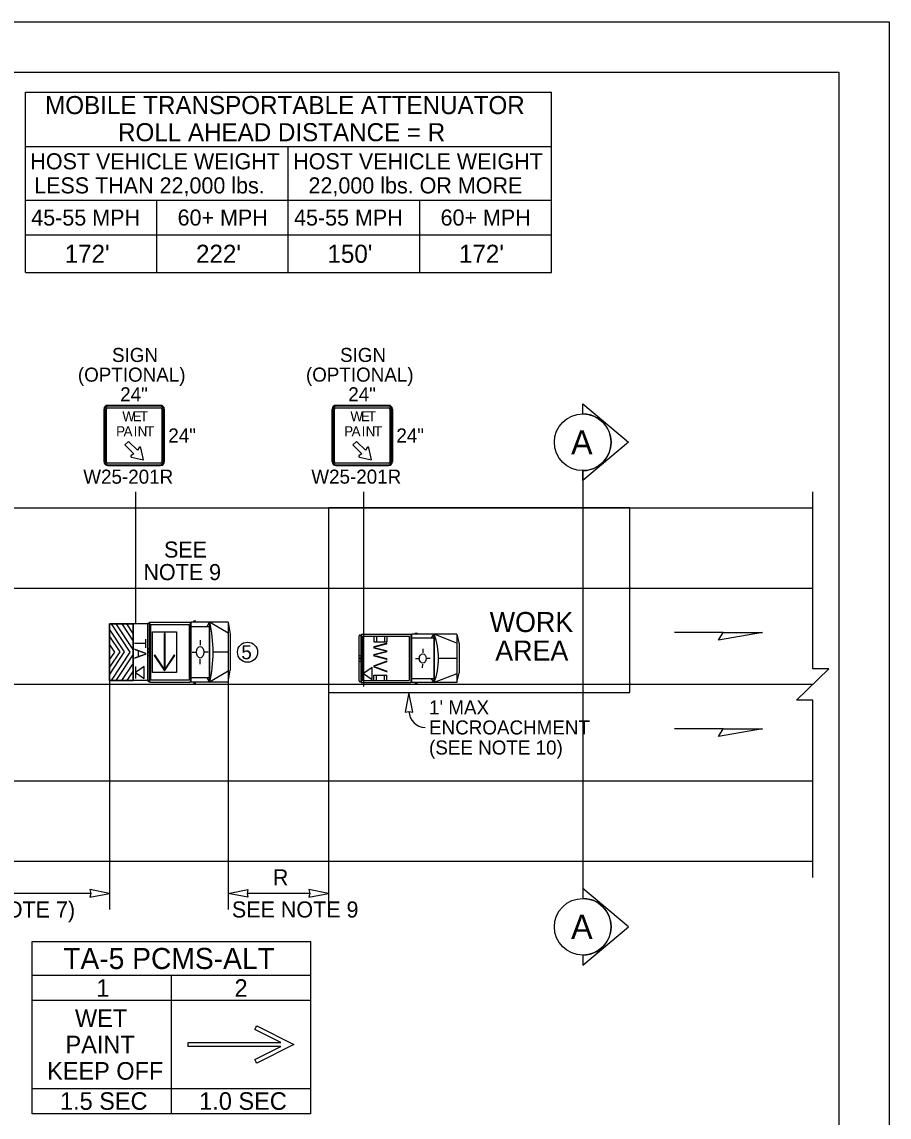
# Model space of a CAD drawing. Extents: x 0 to 17, y 0 to 11.
# Drawn here: x 12.68 to 17, y 5.55 to 11 of the extents above; entities that cross this region are included whole.
import ezdxf

# ---------------------------------------------------------------- set-up
doc = ezdxf.new("R2010")
doc.units = 0
for name, color, linetype in [('RD_ED_ShoulderPavedEdge', 7, 'Continuous'), ('RD_MK_LineEdgeWhite', 7, 'Continuous'), ('RD_MK_LineEdgeYellow', 7, 'Continuous'), ('RD_MK_LineLane', 7, 'Continuous'), ('SH_GI_PlotLimits', 7, 'Continuous'), ('SH_GI_SheetBorder3', 7, 'Continuous'), ('SH_TI_Tables', 7, 'Continuous'), ('SH_TI_WZSectionCut', 7, 'Continuous'), ('TR_SN_ConstructionSigns', 7, 'Continuous'), ('TR_WZ_PortableChangeMessageSign', 7, 'Continuous'), ('TR_WZ_PortableSignMountBlk-Org', 7, 'Continuous'), ('TR_WZ_ProtectiveVehicle', 7, 'Continuous'), ('TR_WZ_TransportableAttenuator', 7, 'Continuous'), ('TR_WZ_WorkZoneDetails', 7, 'Continuous'), ('TR_WZ_WorkZoneTextCurrent', 7, 'Continuous')]:
    doc.layers.add(name, color=color, linetype=linetype)

msp = doc.modelspace()

# ---------------------------------------------------------------- linework, layer by layer
at = {"layer": 'RD_ED_ShoulderPavedEdge'}
for p, q in [((1.8283, 8.5807), (16.62, 8.5807)), ((1.8283, 6.8207), (16.62, 6.8207))]:
    msp.add_line(p, q, dxfattribs=at)
at = {"layer": 'RD_MK_LineEdgeWhite'}
msp.add_line((1.8283, 7.2207), (16.62, 7.2207), dxfattribs=at)
at = {"layer": 'RD_MK_LineEdgeYellow'}
msp.add_line((1.8283, 8.1807), (16.62, 8.1807), dxfattribs=at)
at = {"layer": 'RD_MK_LineLane'}
msp.add_line((16.62, 7.7007), (1.8283, 7.7007), dxfattribs=at)
at = {"layer": 'SH_GI_PlotLimits'}
msp.add_lwpolyline([(0, 11), (17, 11), (17, 0), (0, 0)], close=True, dxfattribs=at)
at = {"layer": 'SH_GI_SheetBorder3'}
for p, q in [((1, 10.75), (16.75, 10.75)), ((16.75, 10.75), (16.75, 0.25))]:
    msp.add_line(p, q, dxfattribs=at)
at = {"layer": 'SH_TI_Tables'}
for p, q in [((12.7019, 9.7515), (12.7019, 10.65)), ((12.7019, 10.65), (15.3188, 10.65)), ((15.3188, 9.7515), (15.3188, 10.65)), ((12.7019, 10.3797), (15.3188, 10.3797)), ((14.0096, 9.7515), (14.0096, 10.3797)), ((12.7019, 10.1123), (14.0096, 10.1123)), ((13.3557, 9.7515), (13.3557, 10.1123)), ((14.0096, 10.1123), (15.3188, 10.1123)), ((14.6642, 9.7515), (14.6642, 10.1123)), ((12.7019, 9.9395), (13.3557, 9.9395)), ((13.3557, 9.9395), (14.0096, 9.9395)), ((14.0096, 9.9395), (14.6642, 9.9395)), ((14.6642, 9.9395), (15.3188, 9.9395)), ((12.7019, 9.7515), (15.3188, 9.7515))]:
    msp.add_line(p, q, dxfattribs=at)
at = {"layer": 'SH_TI_WZSectionCut'}
for p, q in [((15.4753, 9.0481), (15.4753, 9.098)), ((15.4753, 9.098), (15.7034, 8.9069)), ((15.7034, 8.9069), (15.4753, 8.7158)), ((15.4753, 8.7158), (15.4753, 8.7657)), ((15.4753, 8.7657), (15.4753, 6.6358)), ((15.4753, 6.6857), (15.4753, 6.6358)), ((15.7034, 6.4945), (15.4753, 6.6857)), ((15.4753, 6.3034), (15.7034, 6.4945)), ((15.4753, 6.3533), (15.4753, 6.3034))]:
    msp.add_line(p, q, dxfattribs=at)
for centre in [(15.4753, 8.9069), (15.4753, 6.4945)]:
    msp.add_circle(centre, 0.1412, dxfattribs=at)
for centre in [(15.4753, 8.9069), (15.4753, 6.4945)]:
    msp.add_arc(centre, 0.1412, 269.9978, 90.0022, dxfattribs=at)
at = {"layer": 'TR_SN_ConstructionSigns'}
for p, q in [((13.0922, 9.072), (13.0922, 8.8095)), ((13.0922, 8.8095), (13.0922, 9.072)), ((13.0922, 9.072), (13.0922, 8.8095)), ((13.0969, 9.072), (13.0969, 8.8095)), ((13.1047, 8.8095), (13.1047, 9.072)), ((13.3735, 9.0907), (13.111, 9.0907)), ((13.111, 9.0907), (13.3735, 9.0907)), ((13.3735, 9.0907), (13.111, 9.0907)), ((13.3735, 9.086), (13.111, 9.086)), ((13.111, 9.0782), (13.3735, 9.0782)), ((13.3797, 9.072), (13.3797, 8.8095)), ((13.3875, 8.8095), (13.3875, 9.072)), ((13.3922, 8.8095), (13.3922, 9.072)), ((13.3922, 9.072), (13.3922, 8.8095)), ((13.3922, 8.8095), (13.3922, 9.072)), ((14.2274, 9.072), (14.2274, 8.8095)), ((14.2274, 8.8095), (14.2274, 9.072)), ((14.2274, 9.072), (14.2274, 8.8095)), ((14.2321, 9.072), (14.2321, 8.8095)), ((14.2399, 8.8095), (14.2399, 9.072)), ((14.5086, 9.0908), (14.2461, 9.0908)), ((14.2461, 9.0908), (14.5086, 9.0908)), ((14.5086, 9.0908), (14.2461, 9.0908)), ((14.5086, 9.0861), (14.2461, 9.0861)), ((14.2461, 9.0783), (14.5086, 9.0783)), ((14.5149, 9.072), (14.5149, 8.8095)), ((14.5227, 8.8095), (14.5227, 9.072)), ((14.5274, 8.8095), (14.5274, 9.072)), ((14.5274, 9.072), (14.5274, 8.8095)), ((14.5274, 8.8095), (14.5274, 9.072)), ((13.214, 8.9116), (13.1964, 8.8939)), ((13.1964, 8.8939), (13.2406, 8.8497)), ((13.2582, 8.8674), (13.214, 8.9116)), ((14.3492, 8.9116), (14.3315, 8.8939)), ((14.3315, 8.8939), (14.3757, 8.8497)), ((14.3934, 8.8674), (14.3492, 8.9116)), ((13.2406, 8.8497), (13.2271, 8.8416)), ((13.2664, 8.8809), (13.2582, 8.8674)), ((13.2881, 8.8199), (13.2749, 8.8796)), ((14.3757, 8.8497), (14.3622, 8.8416)), ((14.4015, 8.8809), (14.3934, 8.8674)), ((14.4232, 8.8199), (14.4101, 8.8796)), ((13.3735, 8.8032), (13.111, 8.8032)), ((13.111, 8.7954), (13.3735, 8.7954)), ((13.111, 8.7907), (13.3735, 8.7907)), ((13.3735, 8.7907), (13.111, 8.7907)), ((13.111, 8.7907), (13.3735, 8.7907)), ((13.2283, 8.833), (13.2881, 8.8199)), ((14.5086, 8.8033), (14.2461, 8.8033)), ((14.2461, 8.7954), (14.5086, 8.7954)), ((14.2461, 8.7908), (14.5086, 8.7908)), ((14.5086, 8.7908), (14.2461, 8.7908)), ((14.2461, 8.7908), (14.5086, 8.7908)), ((14.3635, 8.833), (14.4232, 8.8199))]:
    msp.add_line(p, q, dxfattribs=at)
for centre, radius, start, end in [((13.111, 9.072), 0.0188, 90, 180), ((13.111, 9.072), 0.0188, 90, 180), ((13.111, 9.072), 0.0188, 90, 180), ((13.111, 9.072), 0.0141, 90, 180), ((13.111, 9.072), 0.00625, 90, 180), ((13.3735, 9.072), 0.0188, 0, 90), ((13.3735, 9.072), 0.0188, 0, 90), ((13.3735, 9.072), 0.0188, 0, 90), ((13.3735, 9.072), 0.0141, 0, 90), ((13.3735, 9.072), 0.00625, 0, 90), ((14.2461, 9.072), 0.0188, 90, 180), ((14.2461, 9.072), 0.0188, 90, 180), ((14.2461, 9.072), 0.0188, 90, 180), ((14.2461, 9.072), 0.0141, 90, 180), ((14.2461, 9.072), 0.00625, 90, 180), ((14.5086, 9.072), 0.0188, 0, 90), ((14.5086, 9.072), 0.0188, 0, 90), ((14.5086, 9.072), 0.0188, 0, 90), ((14.5086, 9.072), 0.0141, 0, 90), ((14.5086, 9.072), 0.00625, 0, 90), ((13.2295, 8.8376), 0.00469, 121.1441, 255.4258), ((13.2704, 8.8784), 0.00469, 14.5742, 148.8559), ((14.3647, 8.8376), 0.00469, 121.1441, 255.4258), ((14.4055, 8.8785), 0.00469, 14.5742, 148.8559), ((13.111, 8.8095), 0.0188, 180, 270), ((13.111, 8.8095), 0.0188, 180, 270), ((13.111, 8.8095), 0.0188, 180, 270), ((13.111, 8.8095), 0.0141, 180, 270), ((13.111, 8.8095), 0.00625, 180, 270), ((13.3735, 8.8095), 0.0141, 270, 0), ((13.3735, 8.8095), 0.00625, 270, 0), ((13.3735, 8.8095), 0.0188, 270, 0), ((13.3735, 8.8095), 0.0188, 270, 0), ((13.3735, 8.8095), 0.0188, 270, 0), ((14.2461, 8.8095), 0.0188, 180, 270), ((14.2461, 8.8095), 0.0188, 180, 270), ((14.2461, 8.8095), 0.0188, 180, 270), ((14.2461, 8.8095), 0.0141, 180, 270), ((14.2461, 8.8095), 0.00625, 180, 270), ((14.5086, 8.8095), 0.0141, 270, 0), ((14.5086, 8.8095), 0.00625, 270, 0), ((14.5086, 8.8095), 0.0188, 270, 0), ((14.5086, 8.8095), 0.0188, 270, 0), ((14.5086, 8.8095), 0.0188, 270, 0)]:
    msp.add_arc(centre, radius, start, end, dxfattribs=at)
at = {"layer": 'TR_WZ_PortableChangeMessageSign'}
for p, q in [((12.7348, 6.4207), (14.1208, 6.4207)), ((12.7348, 5.5639), (12.7348, 6.4207)), ((14.1208, 5.5639), (14.1208, 6.4207)), ((14.1208, 6.2527), (12.7348, 6.2527)), ((13.4278, 5.5639), (13.4278, 6.2527)), ((13.4278, 6.1267), (12.7348, 6.1267)), ((14.1208, 6.1267), (13.4278, 6.1267)), ((13.8528, 6.0017), (14.0368, 5.9083)), ((13.5118, 5.8978), (13.5118, 5.9188)), ((13.5118, 5.9188), (13.9716, 5.9188)), ((13.9716, 5.8978), (13.5118, 5.8978)), ((12.7348, 5.6899), (13.4278, 5.6899)), ((13.4278, 5.6899), (14.1208, 5.6899)), ((14.1208, 5.5639), (12.7348, 5.5639))]:
    msp.add_line(p, q, dxfattribs=at)
for points in [[(13.9716, 5.9188), (13.8434, 5.9829), (13.8481, 5.9923), (13.8528, 6.0017)], [(14.0368, 5.9083), (13.8528, 5.8149), (13.8481, 5.8243), (13.8434, 5.8337), (13.9716, 5.8978)]]:
    msp.add_lwpolyline(points, dxfattribs=at)
at = {"layer": 'TR_WZ_PortableSignMountBlk-Org'}
for p, q in [((13.2487, 7.7904), (13.2487, 7.7304)), ((14.3839, 7.7853), (14.3839, 7.7253))]:
    msp.add_line(p, q, dxfattribs=at)
for points in [[(13.2487, 7.7604), (13.2918, 7.7304), (13.2918, 7.7904)], [(14.3839, 7.7553), (14.427, 7.7253), (14.427, 7.7853)]]:
    msp.add_lwpolyline(points, close=True, dxfattribs=at)
at = {"layer": 'TR_WZ_ProtectiveVehicle'}
for p, q in [((14.3603, 7.9394), (14.3603, 7.722)), ((14.3657, 7.9468), (14.3711, 7.9468)), ((14.3711, 7.9468), (14.3711, 7.7146)), ((14.3719, 7.9507), (14.6187, 7.9507)), ((14.3719, 7.9507), (14.3719, 7.7107)), ((14.3789, 7.9411), (14.3789, 7.7203)), ((14.3789, 7.9411), (14.6117, 7.9411)), ((14.4345, 7.9411), (14.4345, 7.9135)), ((14.4345, 7.9135), (14.5005, 7.9135)), ((14.4477, 7.9411), (14.4477, 7.9135)), ((14.4885, 7.9411), (14.4885, 7.9135)), ((14.5005, 7.9411), (14.5005, 7.9135)), ((14.6117, 7.9411), (14.6117, 7.7203)), ((14.6187, 7.9507), (14.6187, 7.7107)), ((14.622, 7.9507), (14.622, 7.7107)), ((14.8487, 7.9507), (14.622, 7.9507)), ((14.7333, 7.9321), (14.622, 7.9321)), ((14.653, 7.9541), (14.6394, 7.9541)), ((14.7333, 7.9507), (14.7189, 7.9321)), ((14.7333, 7.9507), (14.7333, 7.7107)), ((14.7354, 7.9507), (14.7354, 7.7107)), ((14.8487, 7.9068), (14.7354, 7.9507)), ((14.8487, 7.9507), (14.8487, 7.7107)), ((14.8487, 7.9507), (14.8599, 7.9022)), ((14.6789, 7.8783), (14.6789, 7.8589)), ((14.8599, 7.9022), (14.8599, 7.7591)), ((14.3603, 7.8476), (14.3711, 7.8431)), ((14.3603, 7.8138), (14.3711, 7.8183)), ((14.3632, 7.8307), (14.3682, 7.8307)), ((14.3657, 7.8341), (14.3657, 7.8273)), ((14.6419, 7.8298), (14.6597, 7.8302)), ((14.662, 7.8303), (14.662, 7.8303)), ((14.6781, 7.7845), (14.6784, 7.8026)), ((14.7151, 7.8309), (14.7, 7.8308)), ((14.8487, 7.8307), (14.7576, 7.8307)), ((14.4345, 7.7203), (14.4345, 7.7479)), ((14.4345, 7.7479), (14.5005, 7.7479)), ((14.4477, 7.7203), (14.4477, 7.7479)), ((14.4885, 7.7203), (14.4885, 7.7479)), ((14.5005, 7.7203), (14.5005, 7.7479)), ((14.8487, 7.7546), (14.7354, 7.7107)), ((14.8487, 7.7107), (14.8599, 7.7591)), ((14.3657, 7.7146), (14.3711, 7.7146)), ((14.3719, 7.7107), (14.6187, 7.7107)), ((14.3789, 7.7203), (14.6117, 7.7203)), ((14.7333, 7.7293), (14.622, 7.7293)), ((14.8487, 7.7107), (14.622, 7.7107)), ((14.653, 7.7073), (14.6394, 7.7073)), ((14.7214, 7.7293), (14.7333, 7.7107))]:
    msp.add_line(p, q, dxfattribs=at)
for centre, major_axis, start_param, end_param in [((14.3657, 7.9394), (0, 0.00732), 6.283185, 7.853982), ((14.5734, 7.8307), (0, 0.2518), 4.215852, 5.209111), ((14.3657, 7.722), (0, -0.00732), 4.712389, 6.283185)]:
    msp.add_ellipse(centre, major_axis=major_axis, ratio=0.73155, start_param=start_param, end_param=end_param, dxfattribs=at)
for centre, major_axis in [((14.6789, 7.8307), (0, -0.0231)), ((14.3657, 7.8307), (0, -0.00338))]:
    msp.add_ellipse(centre, major_axis=major_axis, ratio=0.73155, dxfattribs=at)
at = {"layer": 'TR_WZ_TransportableAttenuator'}
for p, q in [((13.1195, 7.9395), (13.1195, 7.976)), ((13.1947, 7.8628), (13.1195, 7.976)), ((13.1195, 7.976), (13.1195, 7.9395)), ((13.1273, 8.0028), (13.1528, 8.0028)), ((13.1273, 8.0028), (13.2209, 7.862)), ((13.1528, 8.0028), (13.1273, 8.0028)), ((13.2375, 7.8744), (13.1528, 8.0028)), ((13.1805, 8.0028), (13.2059, 8.0028)), ((13.2059, 8.0028), (13.1805, 8.0028)), ((13.1805, 8.0028), (13.2375, 7.9159)), ((13.2375, 7.9551), (13.2059, 8.0028)), ((13.318, 8.0028), (13.2375, 8.0028)), ((13.2375, 7.7212), (13.2375, 8.0028)), ((13.3085, 7.9976), (13.3085, 7.7257)), ((13.3129, 8.0067), (13.3173, 8.0067)), ((13.3173, 8.0067), (13.3173, 7.7166)), ((13.318, 8.0117), (13.5211, 8.0117)), ((13.318, 8.0117), (13.318, 7.7117)), ((13.318, 8.0023), (13.318, 7.7212)), ((13.3237, 7.9997), (13.3237, 7.7237)), ((13.3237, 7.9997), (13.5154, 7.9997)), ((13.5154, 7.9997), (13.5154, 7.7237)), ((13.5211, 8.0117), (13.5211, 7.7117)), ((13.5239, 8.0117), (13.5239, 7.7117)), ((13.7104, 8.0117), (13.5239, 8.0117)), ((13.6154, 7.9884), (13.5239, 7.9884)), ((13.5493, 8.0159), (13.5381, 8.0159)), ((13.6154, 8.0117), (13.6036, 7.9884)), ((13.6154, 8.0117), (13.6154, 7.7117)), ((13.6171, 8.0117), (13.6171, 7.7117)), ((13.7104, 7.9567), (13.6171, 8.0117)), ((13.7104, 8.0117), (13.7104, 7.7117)), ((13.7104, 8.0117), (13.7195, 7.9511)), ((13.1195, 7.9395), (13.1706, 7.8632)), ((13.2375, 7.9551), (13.2375, 7.9159)), ((13.2375, 7.9159), (13.2375, 7.9551)), ((13.5707, 7.9211), (13.5706, 7.8969)), ((13.7195, 7.9511), (13.7195, 7.7723)), ((13.1195, 7.8229), (13.1195, 7.9009)), ((13.1456, 7.8621), (13.1195, 7.9009)), ((13.1195, 7.9009), (13.1195, 7.8229)), ((13.1706, 7.8632), (13.1195, 7.7864)), ((13.1195, 7.7496), (13.1947, 7.8628)), ((13.1195, 7.8229), (13.1456, 7.8621)), ((13.2209, 7.862), (13.1272, 7.721)), ((13.2375, 7.8744), (13.2375, 7.8493)), ((13.2375, 7.8493), (13.2375, 7.8744)), ((13.3085, 7.8828), (13.3173, 7.8772)), ((13.3108, 7.8617), (13.3149, 7.8617)), ((13.3129, 7.8659), (13.3129, 7.8574)), ((13.531, 7.8619), (13.5476, 7.8618)), ((13.5521, 7.8611), (13.5521, 7.8611)), ((13.6103, 7.8619), (13.5937, 7.8618)), ((13.7104, 7.8617), (13.6354, 7.8617)), ((13.1523, 7.721), (13.2375, 7.8493)), ((13.2375, 7.8078), (13.1798, 7.721)), ((13.2375, 7.8078), (13.2375, 7.7664)), ((13.2375, 7.7664), (13.2375, 7.8078)), ((13.3085, 7.8405), (13.3173, 7.8462)), ((13.5707, 7.8022), (13.5706, 7.8265)), ((13.1195, 7.7496), (13.1195, 7.7864)), ((13.1195, 7.7864), (13.1195, 7.7496)), ((13.2068, 7.721), (13.2375, 7.7664)), ((13.7104, 7.7666), (13.6171, 7.7117)), ((13.7104, 7.7117), (13.7195, 7.7723)), ((13.1523, 7.721), (13.1272, 7.721)), ((13.1272, 7.721), (13.1523, 7.721)), ((13.2068, 7.721), (13.1798, 7.721)), ((13.1798, 7.721), (13.2068, 7.721)), ((13.318, 7.7212), (13.2375, 7.7212)), ((13.3129, 7.7166), (13.3173, 7.7166)), ((13.318, 7.7117), (13.5211, 7.7117)), ((13.3237, 7.7237), (13.5154, 7.7237)), ((13.6154, 7.7349), (13.5239, 7.7349)), ((13.7104, 7.7117), (13.5239, 7.7117)), ((13.5493, 7.7075), (13.5381, 7.7075)), ((13.6056, 7.7349), (13.6154, 7.7117))]:
    msp.add_line(p, q, dxfattribs=at)
for points in [[(13.2375, 7.721), (13.1195, 7.721), (13.1195, 8.0028), (13.2375, 8.0028)], [(13.3337, 7.9635), (13.4537, 7.9635), (13.4537, 7.7599), (13.3337, 7.7599)], [(13.3917, 7.9553), (13.3917, 7.7783), (13.3957, 7.7783), (13.3957, 7.9553)], [(13.3421, 7.8456), (13.3937, 7.7681), (13.3917, 7.7783), (13.3454, 7.8478)], [(13.3937, 7.7681), (13.4454, 7.8456), (13.4421, 7.8478), (13.3957, 7.7783)], [(13.3937, 7.7681), (13.3957, 7.7783), (13.3917, 7.7783)]]:
    msp.add_lwpolyline(points, close=True, dxfattribs=at)
msp.add_lwpolyline([(13.2375, 8.0028), (13.1195, 8.0028), (13.1195, 7.721), (13.2375, 7.7212)], dxfattribs=at)
for centre, major_axis, start_param, end_param in [((13.3129, 7.9976), (0, 0.00916), 6.283185, 7.853982), ((13.4838, 7.8616), (0, 0.3148), 4.215852, 5.209111), ((13.3129, 7.7258), (0, -0.00916), 4.712389, 6.283185)]:
    msp.add_ellipse(centre, major_axis=major_axis, ratio=0.481608, start_param=start_param, end_param=end_param, dxfattribs=at)
for centre, major_axis, ratio in [((13.3129, 7.8617), (0, -0.00423), 0.481608), ((13.5707, 7.8617), (0, -0.0289), 0.642144), ((13.5707, 7.8617), (0, 0.0289), 0.642144)]:
    msp.add_ellipse(centre, major_axis=major_axis, ratio=ratio, dxfattribs=at)
at = {"layer": 'TR_WZ_WorkZoneDetails'}
for p, q in [((13.2487, 8.6607), (13.2487, 8.0028)), ((14.3839, 8.6607), (14.3839, 7.6908)), ((16.1734, 7.96), (15.9323, 7.96)), ((13.1196, 7.721), (13.1196, 6.5807)), ((13.7103, 7.7113), (13.7103, 6.5808)), ((14.2103, 7.6607), (14.2103, 6.5808)), ((16.1734, 7.48), (15.9323, 7.48)), ((13.0259, 6.6607), (11.7135, 6.6607)), ((14.1166, 6.6608), (13.8041, 6.6608))]:
    msp.add_line(p, q, dxfattribs=at)
msp.add_lwpolyline([(16.62, 6.7407), (16.62, 7.6233), (16.5399, 7.6233), (16.7, 7.7782), (16.62, 7.7782), (16.62, 8.6607)], dxfattribs=at)
for points in [[(14.2103, 8.5807), (14.2103, 7.6607), (15.7103, 7.6607), (15.7103, 8.5807)], [(16.37, 7.96), (16.1512, 7.9214), (16.1734, 7.96)], [(14.6101, 7.6607), (14.5908, 7.5624), (14.6101, 7.567), (14.6294, 7.5624)], [(16.37, 7.48), (16.1512, 7.4414), (16.1734, 7.48)], [(13.1196, 6.6607), (13.0213, 6.68), (13.0259, 6.6607), (13.0213, 6.6415)], [(13.7103, 6.6608), (13.8086, 6.68), (13.8041, 6.6608), (13.8086, 6.6415)], [(14.2103, 6.6608), (14.1121, 6.68), (14.1166, 6.6608), (14.1121, 6.6415)]]:
    msp.add_lwpolyline(points, close=True, dxfattribs=at)
msp.add_circle((13.8064, 7.8615), 0.05, dxfattribs=at)
msp.add_arc((14.692, 7.5689), 0.082, 181.3481, 268.6519, dxfattribs=at)

# ---------------------------------------------------------------- texts
at = {"layer": 'SH_TI_Tables'}
for s, height, p in [('MOBILE TRANSPORTABLE ATTENUATOR', 0.09, (12.7989, 10.5408)), ('ROLL AHEAD DISTANCE = R', 0.09, (13.1619, 10.4058)), ('HOST VEHICLE WEIGHT', 0.08, (12.7254, 10.266)), ('HOST VEHICLE WEIGHT', 0.08, (14.0339, 10.266)), ('LESS THAN 22,000 lbs.', 0.08, (12.7445, 10.146)), ('22,000 lbs. OR MORE', 0.08, (14.1101, 10.146)), ('45-55 MPH', 0.08, (12.73, 9.9859)), ('60+ MPH', 0.08, (13.4585, 9.9859)), ('45-55 MPH', 0.08, (14.0381, 9.9859)), ('60+ MPH', 0.08, (14.7673, 9.9859)), ("172'", 0.09, (12.8963, 9.8005)), ("222'", 0.09, (13.5502, 9.8005)), ("150'", 0.09, (14.2044, 9.8005)), ("172'", 0.09, (14.859, 9.8005))]:
    msp.add_text(s, height=height, rotation=360, dxfattribs=at).set_placement(p)
at = {"layer": 'SH_TI_WZSectionCut'}
for rotation, p in [(359.99, (15.4171, 8.8469)), (0.01, (15.4171, 6.4345))]:
    msp.add_text('A', height=0.12, rotation=rotation, dxfattribs=at).set_placement(p)
at = {"layer": 'TR_SN_ConstructionSigns'}
for s, height, p in [('SIGN', 0.07, (13.1319, 9.3067)), ('SIGN', 0.07, (14.267, 9.3068)), ('(OPTIONAL)', 0.07, (12.9621, 9.2087)), ('(OPTIONAL)', 0.07, (14.0973, 9.2088)), ('24"', 0.07, (13.1727, 9.1107)), ('24"', 0.07, (14.3079, 9.1108)), ('W', 0.05, (13.1832, 9.0116)), ('E', 0.05, (13.2352, 9.0116)), ('T', 0.05, (13.2702, 9.0116)), ('W', 0.05, (14.3184, 9.0116)), ('E', 0.05, (14.3704, 9.0116)), ('T', 0.05, (14.4054, 9.0116)), ('P', 0.05, (13.1525, 8.9366)), ('A', 0.05, (13.1895, 8.9366)), ('I', 0.05, (13.2395, 8.9366)), ('N', 0.05, (13.2595, 8.9366)), ('T', 0.05, (13.301, 8.9366)), ('24"', 0.07, (13.4122, 8.9057)), ('P', 0.05, (14.2876, 8.9366)), ('A', 0.05, (14.3246, 8.9366)), ('I', 0.05, (14.3746, 8.9366)), ('N', 0.05, (14.3946, 8.9366)), ('T', 0.05, (14.4361, 8.9366)), ('24"', 0.07, (14.5474, 8.9058)), ('W25-201R', 0.07, (12.989, 8.7007)), ('W25-201R', 0.07, (14.1241, 8.7008))]:
    msp.add_text(s, height=height, dxfattribs=at).set_placement(p)
at = {"layer": 'TR_WZ_PortableChangeMessageSign'}
for s, height, p in [('TA-5 PCMS-ALT', 0.105, (12.8891, 6.2842)), ('1', 0.0875, (13.0539, 6.146)), ('2', 0.0875, (13.7419, 6.146)), ('WET', 0.0875, (12.9476, 5.9958)), ('PAINT', 0.0875, (12.9005, 5.8646)), ('KEEP OFF', 0.0875, (12.8087, 5.7333)), ('1.5 SEC', 0.0875, (12.8731, 5.5832)), ('1.0 SEC', 0.0875, (13.5661, 5.5832))]:
    msp.add_text(s, height=height, rotation=360, dxfattribs=at).set_placement(p)
at = {"layer": 'TR_WZ_ProtectiveVehicle'}
msp.add_text('WV', height=0.07, rotation=270, dxfattribs=at).set_placement((14.4325, 7.9105))
at = {"layer": 'TR_WZ_TransportableAttenuator'}
msp.add_text('TA', height=0.06, rotation=270, dxfattribs=at).set_placement((13.2423, 7.93))
at = {"layer": 'TR_WZ_WorkZoneDetails'}
for s, height, p in [('WORK', 0.1, (15.012, 7.962)), ('AREA', 0.1, (15.0394, 7.8195)), ('5', 0.07, (13.7757, 7.8265))]:
    msp.add_text(s, height=height, dxfattribs=at).set_placement(p)
at = {"layer": 'TR_WZ_WorkZoneTextCurrent'}
for s, height, p in [('SEE', 0.08, (13.3909, 8.3327)), ('NOTE 9', 0.08, (13.2882, 8.2207)), ("1' MAX", 0.07, (14.7101, 7.5518)), ('ENCROACHMENT', 0.07, (14.7101, 7.452)), ('(SEE NOTE 10)', 0.07, (14.7101, 7.3522)), ('R', 0.08, (13.9327, 6.7008)), ('(VARIES, SEE NOTE 7)', 0.08, (11.795, 6.5407)), ('SEE NOTE 9', 0.08, (13.7285, 6.5408))]:
    msp.add_text(s, height=height, dxfattribs=at).set_placement(p)

doc.saveas('drawing.dxf')
